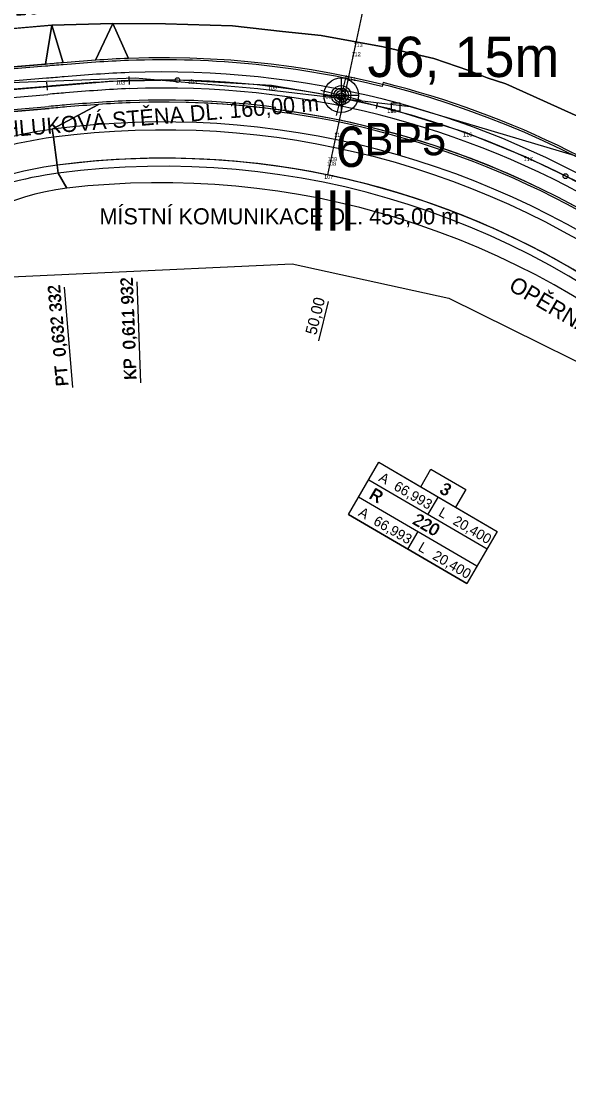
# Model space of a CAD drawing. Extents: x -606444 to -604546, y -1158114 to -1156869.
# Drawn here: x -605380.6 to -605244.8, y -1157370.5 to -1157109.2 of the extents above; entities that cross this region are included whole.
import ezdxf

# ---------------------------------------------------------------- set-up
doc = ezdxf.new("R2010")
doc.units = 0
for name, color, linetype in [('0_sondy', 7, 'Continuous'), ('B_CHOD', 7, 'Continuous'), ('B_TRAM', 7, 'Continuous'), ('B_VOZ', 7, 'Continuous'), ('B_ZELEN', 7, 'Continuous'), ('geofyzikální profily_předběžný GTP', 7, 'Continuous'), ('jádrové vrty_předběžný GTP', 7, 'Continuous'), ('korozní průzkum', 7, 'Continuous'), ('netisk2', 7, 'Continuous'), ('NS_VB', 7, 'Continuous'), ('NS_VB_OBJ', 7, 'Continuous'), ('NS_VB_POP', 7, 'Continuous'), ('OSA', 7, 'Continuous'), ('OSAPOP', 7, 'Continuous'), ('podélný profil trasou tramvaje', 7, 'Continuous'), ('sondy současného průzkumu', 7, 'Continuous'), ('stabilitní profily_předběžný GTP', 7, 'Continuous')]:
    doc.layers.add(name, color=color, linetype=linetype)

# ---------------------------------------------------------------- blocks, each defined once
blk = doc.blocks.new('709')
for p, q in [((0, 2.2), (0, -2.2)), ((-2.2, 0), (2.2, 0))]:
    blk.add_line(p, q)
for radius in [1.2, 0.9, 0.6, 0.3]:
    blk.add_circle((0, 0), radius)
blk = doc.blocks.new('IG vrt podr')
at = {"layer": 'sondy současného průzkumu'}
for p, q in [((0.412, 1.649), (-0.418, -1.672)), ((-1.698, 0.422), (1.644, -0.408))]:
    blk.add_line(p, q, dxfattribs=at)
blk.add_circle((-0.002, 0.001), 1.434, dxfattribs=at)

msp = doc.modelspace()

# ---------------------------------------------------------------- linework, layer by layer
for p, q in [((-605298.09, -1157116.95), (-605298.19, -1157116.85)), ((-605298.09, -1157116.95), (-605297.99, -1157116.85)), ((-605297.61, -1157114.68), (-605297.71, -1157114.58)), ((-605297.61, -1157114.68), (-605297.71, -1157114.78)), ((-605297.61, -1157114.68), (-605297.51, -1157114.58)), ((-605297.61, -1157114.68), (-605297.51, -1157114.78)), ((-605298.09, -1157116.95), (-605298.19, -1157117.05)), ((-605298.09, -1157116.95), (-605297.99, -1157117.05)), ((-605356.23, -1157124.05), (-605356.33, -1157123.95)), ((-605356.23, -1157124.05), (-605356.33, -1157124.15)), ((-605356.23, -1157124.05), (-605356.13, -1157123.95)), ((-605356.23, -1157124.05), (-605356.13, -1157124.15)), ((-605338.33, -1157123.88), (-605338.43, -1157123.78)), ((-605338.33, -1157123.88), (-605338.43, -1157123.98)), ((-605338.33, -1157123.88), (-605338.23, -1157123.78)), ((-605338.33, -1157123.88), (-605338.23, -1157123.98)), ((-605299.4, -1157123.11), (-605299.5, -1157123.01)), ((-605299.4, -1157123.11), (-605299.5, -1157123.21)), ((-605299.4, -1157123.11), (-605299.3, -1157123.01)), ((-605299.4, -1157123.11), (-605299.3, -1157123.21)), ((-605318.55, -1157125.25), (-605318.65, -1157125.15)), ((-605318.55, -1157125.25), (-605318.65, -1157125.35)), ((-605318.55, -1157125.25), (-605318.45, -1157125.15)), ((-605318.55, -1157125.25), (-605318.45, -1157125.35)), ((-605304.97, -1157127.5), (-605305.07, -1157127.4)), ((-605304.97, -1157127.5), (-605305.07, -1157127.6)), ((-605304.97, -1157127.5), (-605304.87, -1157127.4)), ((-605304.97, -1157127.5), (-605304.87, -1157127.6)), ((-605301.24, -1157127.66), (-605301.34, -1157127.56)), ((-605301.24, -1157127.66), (-605301.34, -1157127.76)), ((-605301.24, -1157127.66), (-605301.14, -1157127.56)), ((-605301.24, -1157127.66), (-605301.14, -1157127.76)), ((-605289.22, -1157131.03), (-605289.32, -1157130.93)), ((-605289.22, -1157131.03), (-605289.32, -1157131.13)), ((-605289.22, -1157131.03), (-605289.12, -1157130.93)), ((-605289.22, -1157131.03), (-605289.12, -1157131.13)), ((-605302.36, -1157136.96), (-605302.46, -1157136.86)), ((-605302.36, -1157136.96), (-605302.46, -1157137.06)), ((-605302.36, -1157136.96), (-605302.26, -1157136.86)), ((-605302.36, -1157136.96), (-605302.26, -1157137.06)), ((-605270.4, -1157136.88), (-605270.5, -1157136.78)), ((-605270.4, -1157136.88), (-605270.5, -1157136.98)), ((-605270.4, -1157136.88), (-605270.3, -1157136.78)), ((-605270.4, -1157136.88), (-605270.3, -1157136.98)), ((-605303.63, -1157142.99), (-605303.73, -1157142.89)), ((-605303.63, -1157142.99), (-605303.73, -1157143.09)), ((-605303.63, -1157142.99), (-605303.53, -1157142.89)), ((-605303.63, -1157142.99), (-605303.53, -1157143.09)), ((-605255.42, -1157142.97), (-605255.52, -1157142.87)), ((-605255.42, -1157142.97), (-605255.52, -1157143.07)), ((-605255.42, -1157142.97), (-605255.32, -1157142.87)), ((-605255.42, -1157142.97), (-605255.32, -1157143.07)), ((-605303.87, -1157144.11), (-605303.97, -1157144.01)), ((-605303.87, -1157144.11), (-605303.97, -1157144.21)), ((-605303.87, -1157144.11), (-605303.77, -1157144.01)), ((-605303.87, -1157144.11), (-605303.77, -1157144.21)), ((-605304.56, -1157147.39), (-605304.66, -1157147.29)), ((-605304.56, -1157147.39), (-605304.66, -1157147.49)), ((-605304.56, -1157147.39), (-605304.46, -1157147.29)), ((-605304.56, -1157147.39), (-605304.46, -1157147.49))]:
    msp.add_line(p, q)
at = {"layer": 'B_CHOD'}
for points in [[(-605372.89, -1157136.09), (-605372.63, -1157138.08)], [(-605372.63, -1157138.08), (-605372.89, -1157136.09)], [(-605371.44, -1157147), (-605371.71, -1157145.02)], [(-605371.71, -1157145.02), (-605371.44, -1157147)]]:
    msp.add_lwpolyline(points, dxfattribs=at)
for centre, radius, start, end in [((-605345.26, -1157343.76), 209.5, 53.0471, 97.5799), ((-605358.98, -1157240.67), 105.5, 97.5799, 129.3665), ((-605345.26, -1157343.76), 207.5, 53.0471, 97.5799), ((-605358.98, -1157240.67), 103.5, 97.5799, 129.3665), ((-605358.98, -1157240.67), 96.5, 97.5799, 129.3665), ((-605345.26, -1157343.76), 200.5, 46.8415, 97.5799), ((-605345.26, -1157343.76), 198.5, 46.8415, 97.5799), ((-605358.98, -1157240.67), 94.5, 97.5799, 129.3665)]:
    msp.add_arc(centre, radius, start, end, dxfattribs=at)
at = {"layer": 'B_TRAM'}
for p, q in [((-605374.61, -1157119.95), (-605477.91, -1157128.73)), ((-605476.98, -1157139.69), (-605373.68, -1157130.91))]:
    msp.add_line(p, q, dxfattribs=at)
for centre, radius, start, end in [((-605325, -1157657.47), 539.79, 93.9479, 94.8056), ((-605342.94, -1157397.45), 279.16, 92.2723, 93.9479), ((-605345.33, -1157343.85), 225.5, 51.1864, 92.2057), ((-605200.54, -1159158.03), 2045.5, 94.75838, 94.88187), ((-605325, -1157657.47), 528.79, 93.9479, 94.8061), ((-605342.94, -1157397.45), 268.16, 92.2736, 93.9479), ((-605345.33, -1157343.85), 214.5, 51.3406, 92.204), ((-605200.54, -1159158.03), 2034.5, 94.75825, 94.88192)]:
    msp.add_arc(centre, radius, start, end, dxfattribs=at)
at = {"layer": 'B_VOZ'}
for points in [[(-605372.63, -1157138.08), (-605371.71, -1157145.02)], [(-605371.71, -1157145.02), (-605372.63, -1157138.08)]]:
    msp.add_lwpolyline(points, dxfattribs=at)
for centre, radius, start, end in [((-605345.26, -1157343.76), 207.5, 53.0471, 97.5799), ((-605358.98, -1157240.67), 103.5, 97.5799, 129.3665), ((-605358.98, -1157240.67), 96.5, 97.5799, 129.3665), ((-605345.26, -1157343.76), 200.5, 53.0471, 97.5799)]:
    msp.add_arc(centre, radius, start, end, dxfattribs=at)
at = {"layer": 'B_ZELEN'}
for points in [[(-605450.71, -1157126.42), (-605374.61, -1157119.95), (-605373.01, -1157110.29), (-605388, -1157111.55), (-605418.1, -1157114.11), (-605445.35, -1157116.48), (-605446.98, -1157118.52), (-605450.71, -1157126.42)], [(-605370.22, -1157119.58), (-605373.01, -1157110.29), (-605374.61, -1157119.95)], [(-605362.16, -1157118.96), (-605357.9, -1157109.88), (-605373.01, -1157110.29), (-605370.22, -1157119.58)], [(-605354.01, -1157118.52), (-605357.9, -1157109.88), (-605362.16, -1157118.96)], [(-605203.99, -1157168.14), (-605204.66, -1157157.3), (-605208.8, -1157154.51), (-605207.68, -1157152.85), (-605210.59, -1157150.89), (-605221.99, -1157144.13), (-605243.23, -1157132.55), (-605253.62, -1157127.89), (-605260.44, -1157124.83), (-605265.07, -1157123.34), (-605269.63, -1157121.52), (-605278.31, -1157118.54), (-605290.81, -1157115.61), (-605306.23, -1157112.78), (-605315.84, -1157111.84), (-605328.25, -1157110.41), (-605344.82, -1157109.94), (-605357.9, -1157109.88), (-605354.01, -1157118.52)], [(-605361.41, -1157129.93), (-605361.41, -1157129.93), (-605372.89, -1157136.09)], [(-605372.89, -1157136.09), (-605361.41, -1157129.93)], [(-605373.68, -1157130.91), (-605456.14, -1157137.92), (-605425.89, -1157159.11)], [(-605371.44, -1157147), (-605369.33, -1157150.71)], [(-605369.33, -1157150.71), (-605371.44, -1157147)]]:
    msp.add_lwpolyline(points, dxfattribs=at)
for centre, radius, start, end in [((-605325, -1157657.47), 539.79, 93.9479, 94.8056), ((-605342.94, -1157397.45), 279.16, 92.2723, 93.9479), ((-605345.33, -1157343.85), 225.5, 51.1864, 92.2057), ((-605200.54, -1159158.03), 2045.5, 94.75838, 94.88187), ((-605325, -1157657.47), 528.79, 93.9479, 94.8061), ((-605342.94, -1157397.45), 268.16, 92.2736, 93.9479), ((-605345.33, -1157343.85), 214.5, 53.0445, 92.204), ((-605200.54, -1159158.03), 2034.5, 94.75825, 94.88192), ((-605345.26, -1157343.76), 209.5, 53.0471, 97.5799), ((-605358.98, -1157240.67), 105.5, 97.5799, 129.3665), ((-605345.26, -1157343.76), 198.5, 46.8415, 97.5799), ((-605358.98, -1157240.67), 94.5, 97.5799, 129.3665), ((-605362.33, -1157210.3), 60, 96.6948, 137.3451), ((-605345.97, -1157349.67), 200.33, 48.8336, 96.6948)]:
    msp.add_arc(centre, radius, start, end, dxfattribs=at)
at = {"layer": 'geofyzikální profily_předběžný GTP'}
for points in [[(-605670.78, -1157141.05), (-605656.02, -1157139.47), (-605613.88, -1157139.36), (-605584.8, -1157137.32), (-605531.41, -1157136.33), (-605491.56, -1157133.4), (-605482.07, -1157135.61), (-605438.78, -1157126.66), (-605383.23, -1157124.52), (-605352.34, -1157123.33), (-605321.95, -1157126), (-605284.14, -1157130.42), (-605243.3, -1157142.6), (-605207.83, -1157158.83), (-605179.98, -1157186.15), (-605165.29, -1157202.67), (-605149.23, -1157223.34), (-605135.07, -1157244.47), (-605115.92, -1157286.28), (-605103.22, -1157315.84), (-605095.33, -1157330.32), (-605036.97, -1157403.36), (-604999.08, -1157442.54), (-604970.8, -1157468.35)], [(-605668.89, -1157175.56), (-605638.05, -1157172.71), (-605616.09, -1157172.84), (-605512.92, -1157173.16), (-605468.49, -1157175.65), (-605413.5, -1157174.06), (-605313.44, -1157169.44), (-605274.57, -1157178.01), (-605221.39, -1157204.27), (-605178.57, -1157224), (-605160.32, -1157243.28), (-605143.64, -1157289.5), (-605117.17, -1157349.93), (-605096.21, -1157389.16), (-605065.9, -1157426.81), (-605053.52, -1157443.58), (-605045.82, -1157465.15), (-605020.21, -1157502.2)]]:
    msp.add_lwpolyline(points, dxfattribs=at)
at = {"layer": 'korozní průzkum'}
msp.add_lwpolyline([(-605288.79, -1157129.52), (-605286.7, -1157129.52), (-605286.7, -1157131.56), (-605288.79, -1157131.56)], close=True, dxfattribs=at)
at = {"layer": 'netisk2'}
msp.add_line((-605301.26, -1157127.65), (-605301.39, -1157128.28), dxfattribs=at)
at = {"layer": 'NS_VB'}
for p, q in [((-605388, -1157111.55), (-605373.01, -1157110.29)), ((-605373.01, -1157110.29), (-605357.9, -1157109.88)), ((-605357.9, -1157109.88), (-605344.82, -1157109.94)), ((-605344.82, -1157109.94), (-605328.25, -1157110.41)), ((-605328.25, -1157110.41), (-605315.84, -1157111.84)), ((-605315.84, -1157111.84), (-605306.23, -1157112.78)), ((-605306.23, -1157112.78), (-605290.81, -1157115.61)), ((-605290.81, -1157115.61), (-605278.31, -1157118.54)), ((-605278.31, -1157118.54), (-605269.63, -1157121.52)), ((-605269.63, -1157121.52), (-605265.07, -1157123.34)), ((-605265.07, -1157123.34), (-605260.44, -1157124.83)), ((-605260.44, -1157124.83), (-605253.62, -1157127.89)), ((-605253.62, -1157127.89), (-605243.23, -1157132.55))]:
    msp.add_line(p, q, dxfattribs=at)
for points in [[(-605374.61, -1157119.95), (-605477.91, -1157128.73)], [(-605476.98, -1157139.69), (-605373.68, -1157130.91)]]:
    msp.add_lwpolyline(points, dxfattribs=at)
for centre, radius, start, end in [((-605325, -1157657.47), 539.79, 93.9479, 94.8056), ((-605342.94, -1157397.45), 279.16, 92.2723, 93.9479), ((-605345.33, -1157343.85), 225.5, 51.1864, 92.2057), ((-605200.54, -1159158.03), 2045.5, 94.75838, 94.88187), ((-605325, -1157657.47), 528.79, 93.9479, 94.8061), ((-605342.94, -1157397.45), 268.16, 92.2736, 93.9479), ((-605345.33, -1157343.85), 214.5, 51.3406, 92.204), ((-605200.54, -1159158.03), 2034.5, 94.75825, 94.88192), ((-605345.26, -1157343.76), 209.5, 53.0471, 97.5799), ((-605358.98, -1157240.67), 105.5, 97.5799, 129.3665), ((-605345.26, -1157343.76), 207.5, 53.0471, 97.5799), ((-605358.98, -1157240.67), 103.5, 97.5799, 129.3665), ((-605358.98, -1157240.67), 96.5, 97.5799, 129.3665), ((-605345.26, -1157343.76), 200.5, 16.4017, 97.5799), ((-605345.26, -1157343.76), 198.5, 46.8415, 97.5799), ((-605358.98, -1157240.67), 94.5, 97.5799, 129.3665), ((-605362.33, -1157210.3), 60, 96.6948, 137.3451), ((-605345.97, -1157349.67), 200.33, 48.8336, 96.6948)]:
    msp.add_arc(centre, radius, start, end, dxfattribs=at)
at = {"layer": 'NS_VB_OBJ'}
for points in [[(-605374.57, -1157120.44), (-605477.87, -1157129.23)], [(-605290.84, -1157124.52), (-605291.08, -1157125.49)], [(-605477.02, -1157139.19), (-605373.72, -1157130.41)], [(-605317.71, -1157131.64), (-605317.58, -1157130.65)]]:
    msp.add_lwpolyline(points, dxfattribs=at)
for centre, radius, start, end in [((-605325, -1157657.47), 539.29, 93.9479, 94.8056), ((-605342.94, -1157397.45), 278.66, 92.2723, 93.9479), ((-605345.33, -1157343.85), 225, 76.0474, 92.2056), ((-605200.54, -1159158.02), 2045, 94.75837, 94.88187), ((-605345.33, -1157343.85), 226, 51.1826, 76.0474), ((-605325, -1157657.47), 529.29, 93.9479, 94.806), ((-605342.94, -1157397.45), 268.66, 92.2736, 93.9479), ((-605345.33, -1157343.85), 215, 82.5829, 92.2041), ((-605200.54, -1159158.03), 2035, 94.75826, 94.88192), ((-605345.33, -1157343.85), 214, 51.3884, 82.5829)]:
    msp.add_arc(centre, radius, start, end, dxfattribs=at)
at = {"layer": 'OSA'}
msp.add_line((-605374.15, -1157125.43), (-605584.3, -1157143.3), dxfattribs=at)
for points in [[(-605374.32, -1157123.43), (-605584.46, -1157141.31)], [(-605584.13, -1157145.29), (-605373.98, -1157127.42)]]:
    msp.add_lwpolyline(points, dxfattribs=at)
for centre, radius, start, end in [((-605342.94, -1157397.45), 275.66, 92.2727, 93.9479), ((-605345.33, -1157343.85), 222, 27.1947, 92.2052), ((-605200.54, -1159158.03), 2042, 94.75834, 94.88188), ((-605325, -1157657.47), 536.29, 93.9479, 94.8057), ((-605325, -1157657.47), 534.29, 93.9479, 94.8058), ((-605342.94, -1157397.45), 273.66, 92.2729, 93.9479), ((-605345.33, -1157343.85), 220, 27.1948, 92.2049), ((-605200.54, -1159158.03), 2040, 94.75832, 94.88189), ((-605200.54, -1159158.03), 2038, 94.75829, 94.8819), ((-605325, -1157657.47), 532.29, 93.9479, 94.8059), ((-605342.94, -1157397.45), 271.66, 92.2732, 93.9479), ((-605345.33, -1157343.85), 218, 27.1949, 92.2045)]:
    msp.add_arc(centre, radius, start, end, dxfattribs=at)
at = {"layer": 'OSAPOP'}
for p, q in [((-605374.06, -1157126.42), (-605374.23, -1157124.43)), ((-605353.76, -1157125.01), (-605353.84, -1157123.01)), ((-605292.54, -1157130.9), (-605292.25, -1157129.73)), ((-605350.91, -1157198.96), (-605351.87, -1157173.97)), ((-605367.79, -1157200.16), (-605369.91, -1157175.25)), ((-605306.83, -1157188.55), (-605304.42, -1157178.84)), ((-605291.9, -1157218.71), (-605281.54, -1157224.77)), ((-605294.42, -1157223.03), (-605265.07, -1157240.18)), ((-605281.54, -1157224.77), (-605272.91, -1157229.81)), ((-605267.59, -1157244.5), (-605296.95, -1157227.35)), ((-605277.22, -1157227.29), (-605279.75, -1157231.61)), ((-605299.47, -1157231.66), (-605270.11, -1157248.82)), ((-605272.91, -1157229.81), (-605262.54, -1157235.87)), ((-605282.27, -1157235.92), (-605284.79, -1157240.24))]:
    msp.add_line(p, q, dxfattribs=at)
msp.add_lwpolyline([(-605291.9, -1157218.71), (-605262.54, -1157235.87), (-605270.11, -1157248.82), (-605299.47, -1157231.66)], close=True, dxfattribs=at)
msp.add_lwpolyline([(-605281.54, -1157224.77), (-605279.02, -1157220.45), (-605270.38, -1157225.5), (-605272.91, -1157229.81)], dxfattribs=at)
for centre in [(-605341.87, -1157123.88), (-605245.64, -1157147.73)]:
    msp.add_circle(centre, 0.6, dxfattribs=at)
at = {"layer": 'podélný profil trasou tramvaje'}
msp.add_lwpolyline([(-605085.67, -1157373.96), (-605102.48, -1157348.99), (-605137.42, -1157269.35), (-605142.94, -1157257.48), (-605148.09, -1157246.14), (-605156.56, -1157230.62), (-605167.27, -1157214.45), (-605176.96, -1157202.08), (-605190.28, -1157187.63), (-605201.93, -1157176.87), (-605210.19, -1157170.25), (-605214.51, -1157166.83), (-605234.53, -1157153.68), (-605243.13, -1157148.91), (-605255.42, -1157142.97), (-605270.4, -1157136.88), (-605273.54, -1157135.89), (-605289.22, -1157131.03), (-605304.97, -1157127.5), (-605318.55, -1157125.25), (-605341.87, -1157123.88), (-605358.23, -1157124.22), (-605590.31, -1157143.82)], dxfattribs=at)
at = {"layer": 'stabilitní profily_předběžný GTP'}
msp.add_lwpolyline([(-605304.56, -1157147.37), (-605295.16, -1157103.27)], dxfattribs=at)

# ---------------------------------------------------------------- block references
at = {"layer": '0_sondy', "xscale": 2, "yscale": 2}
msp.add_blockref('709', (-605301.26, -1157127.65), dxfattribs=at)
at = {"layer": 'jádrové vrty_předběžný GTP', "xscale": 3, "yscale": 3}
msp.add_blockref('IG vrt podr', (-605301.24, -1157127.66), dxfattribs=at)

# ---------------------------------------------------------------- texts
for s, height, p in [('112', 1, (-605298.7, -1157117.95)), ('113', 1, (-605298.22, -1157115.68)), ('103', 1, (-605357.17, -1157125.05)), ('104', 1, (-605339.27, -1157124.88)), ('111', 1, (-605299.9, -1157124.11)), ('105', 1, (-605319.49, -1157126.25)), ('106', 1, (-605305.94, -1157128.5)), ('J6', 2, (-605302.69, -1157129.66)), ('115', 1, (-605289.83, -1157132.03)), ('110', 1, (-605303.02, -1157137.96)), ('116', 1, (-605271.04, -1157137.88)), ('109', 1, (-605304.57, -1157143.99)), ('117', 1, (-605256.03, -1157143.97)), ('108', 1, (-605304.81, -1157145.11)), ('107', 1, (-605305.5, -1157148.39))]:
    msp.add_text(s, height=height).set_placement(p)
at = {"layer": '0_sondy'}
msp.add_text('6', height=10, dxfattribs=at).set_placement((-605302.62, -1157145.42))
at = {"layer": 'jádrové vrty_předběžný GTP'}
msp.add_text('J6, 15m', height=10, dxfattribs=at).set_placement((-605294.72, -1157123.12))
at = {"layer": 'korozní průzkum'}
msp.add_text('BP5', height=8, dxfattribs=at).set_placement((-605295.46, -1157142.53))
at = {"layer": 'NS_VB_POP'}
for s, rotation, p in [('NÍZKÁ PROTIHLUKOVÁ STĚNA DL. 190,00 m', 4.8613, (-605419.5, -1157111.16)), ('NÍZKÁ PROTIHLUKOVÁ STĚNA DL. 160,00 m', 4.8613, (-605418.29, -1157140.98)), ('OPĚRNÁ ZEĎ DL. 322,50 m', 329.5835, (-605259.99, -1157175.79))]:
    msp.add_text(s, height=4, rotation=rotation, dxfattribs=at).set_placement(p)
msp.add_text('MÍSTNÍ KOMUNIKACE DL. 455,00 m', height=4, dxfattribs=at).set_placement((-605361.19, -1157159.68))
at = {"layer": 'OSAPOP'}
for s, height, rotation, p in [('KP  0,611 932', 3, 92.2049, (-605352.1, -1157198.1)), ('KP  0,611 932', 3, 92.2049, (-605351.94, -1157198.25)), ('PT  0,632 332', 3, 94.8613, (-605368.99, -1157199.61)), ('PT  0,632 332', 3, 94.8613, (-605368.83, -1157199.74)), ('50,00', 2.8, 76.0756, (-605307.48, -1157187.28)), ('A', 2.5, 329.6998, (-605292.16, -1157223.19)), ('66,993', 2.5, 329.6998, (-605288.44, -1157225.37)), ('3', 3, 329.6998, (-605277.15, -1157226.17)), ('3', 3, 329.6998, (-605276.94, -1157226.12)), ('R', 3, 329.6998, (-605294.63, -1157227.54)), ('R', 3, 329.6998, (-605294.42, -1157227.49)), ('A', 2.5, 329.6998, (-605297.21, -1157231.83)), ('220', 3, 329.6998, (-605283.86, -1157233.83)), ('220', 3, 329.6998, (-605283.66, -1157233.78)), ('L', 2.5, 329.6998, (-605277.34, -1157231.85)), ('66,993', 2.5, 329.6998, (-605293.49, -1157234)), ('20,400', 2.5, 329.6998, (-605273.77, -1157233.94)), ('L', 2.5, 329.6998, (-605282.39, -1157240.49)), ('20,400', 2.5, 329.6998, (-605278.81, -1157242.58))]:
    msp.add_text(s, height=height, rotation=rotation, dxfattribs=at).set_placement(p)
at = {"layer": 'stabilitní profily_předběžný GTP'}
msp.add_text('III', height=10, dxfattribs=at).set_placement((-605308.9, -1157161.27))

doc.saveas('drawing.dxf')
